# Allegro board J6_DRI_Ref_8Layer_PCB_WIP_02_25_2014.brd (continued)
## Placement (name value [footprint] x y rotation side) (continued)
TP1MA1  TP_VIA_MEM3  [TP1-18RD8]  34.28 26.49 0 top
TP1MA2  TP_VIA_MEM3  [TP1-18RD8]  36.73 25.75 0 top
TP1MA3  TP_VIA_MEM3  [TP1-18RD8]  31.8 25.7 0 top
TP1MA4  TP_VIA_MEM3  [TP1-18RD8]  34.28 25.69 0 top
TP1MA5  TP_VIA_MEM3  [TP1-18RD8]  28.68 25.69 0 top
TP1MA6  TP_VIA_MEM3  [TP1-18RD8]  31.08 25.69 0 top
TP1MA7  TP_VIA_MEM3  [TP1-18RD8]  30.28 24.89 0 top
TP1MA8  TP_VIA_MEM3  [TP1-18RD8]  33.17 24.21 0 top
TP1MA9  TP_VIA_MEM3  [TP1-18RD8]  29.48 24.09 0 top
TP1MA10  TP_VIA_MEM3  [TP1-18RD8]  30.28 24.09 0 top
TP1MA11  TP_VIA_MEM3  [TP1-18RD8]  34.28 24.09 0 top
TP1MA12  TP_VIA_MEM3  [TP1-18RD8]  35.08 23.29 0 top
TP1MA13  TP_VIA_MEM3  [TP1-18RD8]  33.05 22.63 0 top
TP1MA14  TP_VIA_MEM3  [TP1-18RD8]  30.28 22.49 0 top
TP1MA15  TP_VIA_MEM3  [TP1-18RD8]  31.73 22.42 0 top
TP1MA16  TP_VIA_MEM3  [TP1-18RD8]  36.54 21.95 0 top
TP1MA17  TP_VIA_MEM3  [TP1-18RD8]  30.28 21.69 0 top
TP1MA18  TP_VIA_MEM3  [TP1-18RD8]  34.28 21.69 0 top
TP1MA19  TP_VIA_MEM3  [TP1-18RD8]  31.78 21.4 0 top
TP1MA20  TP_VIA_MEM3  [TP1-18RD8]  33.3 20.91 0 top
TP1MA21  TP_VIA_MEM3  [TP1-18RD8]  29.48 20.89 0 top
TP1MA22  TP_VIA_MEM3  [TP1-18RD8]  35.08 20.09 0 top
TP1MA23  TP_VIA_MEM3  [TP1-18RD8]  31.08 19.84 0 top
TP1MA24  TP_VIA_MEM3  [TP1-18RD8]  33.43 19.76 0 top
TP1MA25  TP_VIA_MEM3  [TP1-18RD8]  30.43 19.57 0 top
TP1MA26  TP_VIA_MEM3  [TP1-18RD8]  34.06 19 0 top
TP1MA27  TP_VIA_MEM3  [TP1-18RD8]  31.48 18.49 0 top
TP1MB1  TP_VIA_MEM3  [TP1-18RD8]  46.98 26.49 0 top
TP1MB2  TP_VIA_MEM3  [TP1-18RD8]  49.43 25.75 0 top
TP1MB3  TP_VIA_MEM3  [TP1-18RD8]  44.5 25.7 0 top
TP1MB4  TP_VIA_MEM3  [TP1-18RD8]  46.98 25.69 0 top
TP1MB5  TP_VIA_MEM3  [TP1-18RD8]  41.38 25.69 0 top
TP1MB6  TP_VIA_MEM3  [TP1-18RD8]  43.78 25.69 0 top
TP1MB7  TP_VIA_MEM3  [TP1-18RD8]  42.98 24.89 0 top
TP1MB8  TP_VIA_MEM3  [TP1-18RD8]  45.87 24.21 0 top
TP1MB9  TP_VIA_MEM3  [TP1-18RD8]  42.18 24.09 0 top
TP1MB10  TP_VIA_MEM3  [TP1-18RD8]  42.98 24.09 0 top
TP1MB11  TP_VIA_MEM3  [TP1-18RD8]  46.98 24.09 0 top
TP1MB12  TP_VIA_MEM3  [TP1-18RD8]  47.78 23.29 0 top
TP1MB13  TP_VIA_MEM3  [TP1-18RD8]  45.75 22.63 0 top
TP1MB14  TP_VIA_MEM3  [TP1-18RD8]  42.98 22.49 0 top
TP1MB15  TP_VIA_MEM3  [TP1-18RD8]  44.43 22.42 0 top
TP1MB16  TP_VIA_MEM3  [TP1-18RD8]  49.24 21.95 0 top
TP1MB17  TP_VIA_MEM3  [TP1-18RD8]  42.98 21.69 0 top
TP1MB18  TP_VIA_MEM3  [TP1-18RD8]  46.98 21.69 0 top
TP1MB19  TP_VIA_MEM3  [TP1-18RD8]  44.48 21.4 0 top
TP1MB20  TP_VIA_MEM3  [TP1-18RD8]  46 20.91 0 top
TP1MB21  TP_VIA_MEM3  [TP1-18RD8]  42.18 20.89 0 top
TP1MB22  TP_VIA_MEM3  [TP1-18RD8]  47.78 20.09 0 top
TP1MB23  TP_VIA_MEM3  [TP1-18RD8]  43.78 19.84 0 top
TP1MB24  TP_VIA_MEM3  [TP1-18RD8]  46.13 19.76 0 top
TP1MB25  TP_VIA_MEM3  [TP1-18RD8]  43.13 19.57 0 top
TP1MB26  TP_VIA_MEM3  [TP1-18RD8]  46.76 19 0 top
TP1MB27  TP_VIA_MEM3  [TP1-18RD8]  44.18 18.49 0 top
TP1MC1  TP_VIA_MEM2  [TP1-18RD8]  56.65 27.07 0 top
TP1MC2  TP_VIA_MEM2  [TP1-18RD8]  58.25 27.07 0 top
TP1MC3  TP_VIA_MEM2  [TP1-18RD8]  60.65 27.07 0 top
TP1MC4  TP_VIA_MEM2  [TP1-18RD8]  58.25 26.27 0 top
TP1MC5  TP_VIA_MEM2  [TP1-18RD8]  55.05 25.45 0 top
TP1MC6  TP_VIA_MEM2  [TP1-18RD8]  57.74 25.45 0 top
TP1MC7  TP_VIA_MEM2  [TP1-18RD8]  56.03 24.72 0 top
TP1MC8  TP_VIA_MEM2  [TP1-18RD8]  54.25 24.65 0 top
TP1MC9  TP_VIA_MEM2  [TP1-18RD8]  58.25 24.65 0 top
TP1MC10  TP_VIA_MEM2  [TP1-18RD8]  54.25 23.85 0 top
TP1MC11  TP_VIA_MEM2  [TP1-18RD8]  55.05 23.85 0 top
TP1MC12  TP_VIA_MEM2  [TP1-18RD8]  59.85 23.85 0 top
TP1MC13  TP_VIA_MEM2  [TP1-18RD8]  54.25 23.05 0 top
TP1MC14  TP_VIA_MEM2  [TP1-18RD8]  55.85 23.05 0 top
TP1MC15  TP_VIA_MEM2  [TP1-18RD8]  58.25 23.05 0 top
TP1MC16  TP_VIA_MEM2  [TP1-18RD8]  58.25 22.25 0 top
TP1MC17  TP_VIA_MEM2  [TP1-18RD8]  59.05 22.25 0 top
TP1MC18  TP_VIA_MEM2  [TP1-18RD8]  54.25 21.45 0 top
TP1MC19  TP_VIA_MEM2  [TP1-18RD8]  55.85 21.45 0 top
TP1MC20  TP_VIA_MEM2  [TP1-18RD8]  58.25 21.45 0 top
TP1MC21  TP_VIA_MEM2  [TP1-18RD8]  59.05 21.45 0 top
TP1MC22  TP_VIA_MEM2  [TP1-18RD8]  55.05 20.65 0 top
TP1MC23  TP_VIA_MEM2  [TP1-18RD8]  55.85 19.85 0 top
TP1MC24  TP_VIA_MEM2  [TP1-18RD8]  58.25 19.85 0 top
TP1MC25  TP_VIA_MEM2  [TP1-18RD8]  59.05 19.85 0 top
TP1MC26  TP_VIA_MEM2  [TP1-18RD8]  55.91 19 0 top
TP2  NP  [TP20]  46.81 179.66 270 top
TP2MA1  TP_VIA_MEM0  [TP1-18RD8]  81.05 28.04 180 top
TP2MA2  TP_VIA_MEM0  [TP1-18RD8]  81.41 27.56 180 top
TP2MA3  TP_VIA_MEM0  [TP1-18RD8]  82.22 27.54 180 top
TP2MA4  TP_VIA_MEM0  [TP1-18RD8]  82.07 26.9 180 top
TP2MA5  TP_VIA_MEM0  [TP1-18RD8]  80.67 26.7 180 top
TP2MA6  TP_VIA_MEM0  [TP1-18RD8]  81.31 26.49 180 top
TP2MA7  TP_VIA_MEM0  [TP1-18RD8]  82.14 25.94 180 top
TP2MA8  TP_VIA_MEM0  [TP1-18RD8]  80.72 25.86 180 top
TP2MA9  TP_VIA_MEM0  [TP1-18RD8]  81.37 25.35 180 top
TP2MA10  TP_VIA_MEM0  [TP1-18RD8]  80.8 24.97 180 top
TP2MA11  TP_VIA_MEM0  [TP1-18RD8]  82.19 24.72 180 top
TP2MA12  TP_VIA_MEM0  [TP1-18RD8]  81.56 24.34 0 top
TP2MA13  TP_VIA_MEM0  [TP1-18RD8]  80.72 24.11 180 top
TP2MA14  TP_VIA_MEM0  [TP1-18RD8]  82.07 23.65 180 top
TP2MA15  TP_VIA_MEM0  [TP1-18RD8]  81.05 23.32 180 top
TP2MA16  TP_VIA_MEM0  [TP1-18RD8]  81.43 22.81 180 top
TP2MA17  TP_VIA_MEM0  [TP1-18RD8]  82.07 22.68 180 top
TP2MA18  TP_VIA_MEM0  [TP1-18RD8]  80.67 22.28 180 top
TP2MA19  TP_VIA_MEM0  [TP1-18RD8]  81.94 21.74 180 top
TP2MA20  TP_VIA_MEM0  [TP1-18RD8]  81.33 21.54 180 top
TP2MA21  TP_VIA_MEM0  [TP1-18RD8]  80.85 21.19 180 top
TP2MA22  TP_VIA_MEM0  [TP1-18RD8]  81.74 20.65 180 top
TP2MA23  TP_VIA_MEM0  [TP1-18RD8]  82.63 20.37 180 top
TP2MA24  TP_VIA_MEM0  [TP1-18RD8]  81.15 20.35 180 top
TP2MA25  TP_VIA_MEM0  [TP1-18RD8]  81.94 19.51 180 top
TP2MA26  TP_VIA_MEM0  [TP1-18RD8]  82.58 19.51 180 top
TP2MA27  TP_VIA_MEM0  [TP1-18RD8]  80.29 19.26 180 top
TP2MB1  TP_VIA_MEM1  [TP1-18RD8]  95.4 28.04 180 top
TP2MB2  TP_VIA_MEM1  [TP1-18RD8]  95.76 27.56 180 top
TP2MB3  TP_VIA_MEM1  [TP1-18RD8]  96.57 27.54 180 top
TP2MB4  TP_VIA_MEM1  [TP1-18RD8]  96.42 26.9 180 top
TP2MB5  TP_VIA_MEM1  [TP1-18RD8]  95.02 26.7 180 top
TP2MB6  TP_VIA_MEM1  [TP1-18RD8]  95.66 26.49 180 top
TP2MB7  TP_VIA_MEM1  [TP1-18RD8]  96.49 25.96 180 top
TP2MB8  TP_VIA_MEM1  [TP1-18RD8]  95.07 25.86 180 top
TP2MB9  TP_VIA_MEM1  [TP1-18RD8]  95.72 25.35 180 top
TP2MB10  TP_VIA_MEM1  [TP1-18RD8]  95.15 24.97 180 top
TP2MB11  TP_VIA_MEM1  [TP1-18RD8]  96.55 24.72 180 top
TP2MB12  TP_VIA_MEM1  [TP1-18RD8]  95.91 24.34 0 top
TP2MB13  TP_VIA_MEM1  [TP1-18RD8]  95.07 24.11 180 top
TP2MB14  TP_VIA_MEM1  [TP1-18RD8]  96.42 23.65 180 top
TP2MB15  TP_VIA_MEM1  [TP1-18RD8]  95.4 23.32 180 top
TP2MB16  TP_VIA_MEM1  [TP1-18RD8]  95.78 22.81 180 top
TP2MB17  TP_VIA_MEM1  [TP1-18RD8]  96.42 22.68 180 top
TP2MB18  TP_VIA_MEM1  [TP1-18RD8]  95.02 22.28 180 top
TP2MB19  TP_VIA_MEM1  [TP1-18RD8]  96.29 21.74 180 top
TP2MB20  TP_VIA_MEM1  [TP1-18RD8]  95.68 21.54 180 top
TP2MB21  TP_VIA_MEM1  [TP1-18RD8]  95.2 21.19 180 top
TP2MB22  TP_VIA_MEM1  [TP1-18RD8]  96.09 20.65 180 top
TP2MB23  TP_VIA_MEM1  [TP1-18RD8]  96.98 20.37 180 top
TP2MB24  TP_VIA_MEM1  [TP1-18RD8]  95.5 20.35 180 top
TP2MB25  TP_VIA_MEM1  [TP1-18RD8]  96.29 19.51 180 top
TP2MB26  TP_VIA_MEM1  [TP1-18RD8]  96.93 19.51 180 top
TP2MB27  TP_VIA_MEM1  [TP1-18RD8]  94.64 19.26 180 top
TP2MC1  TP_VIA_MEM2  [TP1-18RD8]  53.07 26.25 0 top
TP22  NP  [TP20]  0.97 87.45 270 top
TP23  NP  [TP20]  12.65 86.95 270 top
TP24  NP  [TP20]  118.31 85.04 180 top
TP27  NP  [TP20]  26.49 94.82 0 top
TP30  NP  [TP20]  134.95 84.91 180 top
TP31  NP  [TP20]  134.95 85.93 180 top
TP32  NP  [TP20]  118.31 86.18 180 top
TP39  NP  [TP20]  30.56 77.93 0 top
TP41  NP  [TP20]  118.82 69.29 180 top
TP42  NP  [TP20]  125.55 65.86 180 top
TP43  NP  [TP20]  127.71 65.86 180 top
TP44  NP  [TP20]  0.97 65.61 270 top
TP45  NP  [TP20]  13.16 65.36 270 top
TP46  NP  [TP20]  0.97 64.59 270 top
TP47  NP  [TP20]  12.65 64.59 270 top
TP48  NP  [TP20]  13.16 63.83 270 top
TP49  NP  [TP20]  0.97 63.58 270 top
TP51  NP  [TP20]  157.53 217.15 0 top
TP52  NP  [TP20]  37.67 60.91 0 top
TP54  NP  [TP20]  162 217.15 0 top
TP55  NP  [TP20]  38.81 57.74 0 top
TP57  NP  [TP20]  39.07 51.13 0 top
TP58  NP  [TP20]  160.88 217.15 0 top
TP59  NP  [TP20]  159.77 217.15 0 top
TP60  NP  [TP20]  158.65 217.15 0 top
TP61  NP  [TP20]  6.81 41.73 270 top
TP62  NP  [TP20]  124.54 25.86 0 top
TP63  NP  [TP20]  2.54 15.24 0 top
TP64  NP  [TP20]  6.81 15.24 180 top
TP76  NP  [TP20]  156.41 217.15 0 top
TP77  NP  [TP20]  155.3 217.15 0 top
TP78  NP  [TP20]  154.18 217.15 0 top
TP97  TESTPOINT  [TP1-18RD8]  165.2 217.12 0 top
TP98  TESTPOINT  [TP1-18RD8]  164.14 217.12 0 top
TP99  TESTPOINT  [TP1-18RD8]  163.09 217.12 0 top
TP100  TESTPOINT  [TP1-18RD8]  153.09 217.12 0 top
TP101  TESTPOINT  [TP1-18RD8]  147.81 217.12 0 top
TP102  TESTPOINT  [TP1-18RD8]  148.86 217.12 0 top
TP103  TESTPOINT  [TP1-18RD8]  144.64 217.12 0 top
TP104  TESTPOINT  [TP1-18RD8]  146.75 217.12 0 top
TP105  TESTPOINT  [TP1-18RD8]  149.92 217.12 0 top
TP106  TESTPOINT  [TP1-18RD8]  143.58 217.12 0 top
TP107  TESTPOINT  [TP1-18RD8]  145.69 217.12 0 top
TP108  TESTPOINT  [TP1-18RD8]  150.98 217.12 0 top
TP109  TESTPOINT  [TP1-18RD8]  152.03 217.12 0 top
TP110  TESTPOINT  [TP1-18RD8]  166.26 217.12 0 top
U3  DS90UR905QSQE/NOPB  [QFN48-11X35]  110.31 160.48 90 top
U6  74LVC1G08DCK  [DCK-5]  106.5 146 270 top
U8  RBO40_40G  [DPAK3-55X120-4]  160.48 159.21 270 top
U18  S25FL256SAGMFV001  [SO16-25X75-300]  83.26 112.73 90 top
U23  TPS43351QDAPRQ1  [DAP38]  149.81 115.52 270 top
U35  SN74AVC8T245RHL  [RHL24-PVQFN-TI]  16.33 92.92 90 top
U36  TPS2065D  [SO8-25X75]  25.86 90.5 270 top
U37  TPS3808G09DBVR  [DBV6-27X39-6]  137.49 89.11 0 top
U41  SN74AVC4T245RGYR  [RGY16-12X34]  16.33 84.91 90 top
U43  TPS2065D  [SO8-25X75]  25.86 81.87 270 top
U44  TPS3808G09DBVR  [DBV6-27X39-6]  43.13 81.36 90 top
U45  TPS659039  [ZWS169-13P8]  127.58 77.42 0 top
U46  SN74AVC8T245RHL  [RHL24-PVQFN-TI]  16.33 77.29 90 top
U48  SN74AVC4T245RGYR  [RGY16-12X34]  16.33 69.29 90 top
U50  PCA9306/PCA9306-Q1  [DCU8-10X50]  16.46 62.44 180 top
U52  DRA7XX  [BGA-ZKK-6334-P760]  67.13 58.85 270 top
U54  HVDA551-Q1  [SO8-25X75]  15.06 54.43 270 top
U55  TPS77018DBVT  [DBV5-27X39]  159.33 51.39 180 top
U56  TPS74801  [DRC10-11X33]  4.14 51.26 0 top
U59  TLV320AIC3106  [RGZ48-11X34]  149.68 45.8 270 top
U62  74LVC1G08DCK  [DCK-5]  102.31 40.59 90 top
U63  TPS57112QRTERQ1  [RTE16-12X34]  8.08 38.31 270 top
U64  TPS51200  [DRC10-11X33]  6.81 27.76 0 top
U65  MT41K256M16HA-125 IT:E  [BGA6X16-P8-RE-PKG]  32.28 26.49 0 top
U66  MT41K256M16HA-125 IT:E  [BGA6X16-P8-RE-PKG]  44.98 26.49 0 top
U67  MT41K128M8JP-15E:AAT  [BGA6X13-P8-RA-PKG]  57.05 25.86 0 top
U68  MT41K256M8DA-15E:M ATT  [BGA6X13-P8-RA-PKG]  81.43 25.86 0 top
U69  MT41K256M8DA-15E:M ATT  [BGA6X13-P8-RA-PKG]  95.78 25.86 0 top
U72  TPD4S014DSQ  [DSQ10-SON]  59.77 175.21 270 bottom
U73  TPD4S014DSQ  [DSQ10-SON]  44.91 176.99 270 bottom
U77  TPD2E001DRL-Q1  [DRL5-12X40]  140.28 158.32 0 bottom
U78  TPD2E001DRL-Q1  [DRL5-12X40]  135.71 158.32 0 bottom
U79  TPD2E001DRL-Q1  [DRL5-12X40]  131.14 158.32 0 bottom
U92  TPS22965DSG  [DSG8-11X20]  122.38 102.31 0 bottom
U100  TXS0108EPW  [PW20-14X70]  6.81 75.39 180 bottom
U101  SN74AVC2T45DCT  [DCT8-14X70]  136.47 67.26 270 bottom
U102  TPS3808G09DBVR  [DBV6-27X39-6]  109.04 66.63 180 bottom
U104  SN74LVC1T45  [DCK-17X60-6]  7.32 63.83 90 bottom
U105  24WC256  [SO8-25X75-295]  161.49 61.8 0 bottom
U110  SN74LVC1G04DCK  [DCK-5]  13.79 56.21 90 bottom
U115  MT41K256M8DA-15E:M ATT  [BGA6X13-P8-RA-PKG]  95.78 25.86 180 bottom
U116  MT41K256M8DA-15E:M ATT  [BGA6X13-P8-RA-PKG]  81.43 25.86 180 bottom
U117  TMP102AIDRLT  [DRL6-12X30]  67 197.26 0 top
U121  MTFC16GJVEC-4M-169WFBGA  [FBGA153-169-P5-COMBO]  7.43 204.98 0 top
U122  SN65HVDA100-Q1  [SO8-25X75]  127.33 158.32 0 bottom
U123  HVDA551-Q1  [SO8-25X75]  123.52 161.75 180 bottom
U129  74LVC1G08DCK  [DCK-5]  69.83 197.38 0 top
U130  74LVC1G08DCK  [DCK-5]  72.71 197.38 0 top
U131  TPD2E001DRL-Q1  [DRL5-12X40]  75.58 197.38 0 top
U132  TVP5150AM1  [PBS32-12X57]  19.37 200.18 0 top
Y3  32.768KHz  [XTAL4-23X47-SSP-T7]  37.41 63.45 180 top
Y4  Crystal_CM519_CTS407  [XTAL2-CM519-DUAL-CTS407]  134.19 61.55 0 top
Y5  22.5792MHz  [XTAL4-55X87]  32.72 59.39 0 top
Y6  20MHz  [XTAL2-75X94]  42.49 57.36 90 top
Y7  14.31818MHz  [XTAL2-75X94]  53.04 144.73 90 bottom

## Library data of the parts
C5 C6 = CAP: Tolerance: TOLERANCE; User Part Number: USERPART#; signal model: CAP_C402_25_0_1UF_0_1uF
C7 C8 C13 C60 C61 C72 C77 C104 C136 C140 C158 C210-C212 C214 C228 C229 C233-C235 C295 C299 C300 C318 C319 C355 C357 C382 C406 C436 C493 C548 C556 C557 C560 C562 C564 C569 C571 C572 C576 C577 C589 C655-C657 C665 C670 C673 C678 = CAP: Tolerance: X; User Part Number: X
C14-C16 C269 C290 C693 C787 = Cap 100nF Cermc 16V 10% 603_4: Tolerance: TOLERANCE; User Part Number: USERPART#
C45 C47 C49 C50 C440 C462 C468 C480 C481 C501 C504 C509 C519 C520 C529 C734 = CAP NP: Tolerance: X; User Part Number: X
C51 = CAP_POL: Tolerance: X; User Part Number: X
C52 C62 C63 C154 C156 C174 C188 C191 C192 C201 C202 C503 C546 = CAP NP: User Part Number: X; Tolerance: X
C67 = CAP NP: Tolerance: TOLERANCE; User Part Number: USERPART#; room: SPI FLASH
C71 C74 C683 = C_0: Tolerance: X; User Part Number: X
C76 C78 C110 C117 C137-C139 C143 C148 C231 C232 C273 C280 C301-C307 C309 C314 C329 C330 C348 C485 C508 C514 C521 C522 C528 C535 C537 C541 C549 C550 C553 C559 C563 C570 C574 C578 C580 C584 C609 C708 C716-C721 C785 C786 C792-C794 C797 C800 C801 = CAP: Tolerance: TOLERANCE; User Part Number: USERPART#
C79 C86 C213 C325 C340 C356 C460 = CAP: User Part Number: X; Tolerance: X
C80 = CAP NP: User Part Number: USERPART#; Tolerance: TOLERANCE; room: USB
C87 C89 C107 C109 C112 C118 C119 C149 C150 C155 C157 C179 C186 C187 C365 C366 C369 C372 C384 C385 C387 C389 C396 C405 C411 C435 C463 C466 C469 C473-C475 C492 C495 C532 C579 C607 C658 C659 = CAP NP: User Part Number: USERPART#; Tolerance: TOLERANCE
C90-C96 C105 C108 C111 C359 C360 C367 C373 C374 C393-C395 C453 C456 C465 C478 C483 C487 = NPCap_0: User Part Number: X; Tolerance: X
C99 C101-C103 C346 C352 C381 C403 C407 C408 C430 C431 C433 = C_2.2uF/0402/6.3V_X5R_0402: User Part Number: USERPART#; Tolerance: TOLERANCE
C100 C434 = C_100nF/0402/6.3V_X5R_0402: User Part Number: USERPART#; Tolerance: TOLERANCE
C106 C113 = Cap 18pF Cermc 50V 5% 603_0: User Part Number: USERPART#; Tolerance: TOLERANCE
C115 C116 = C_12pF/0402/50V_COG_0402: User Part Number: USERPART#; Tolerance: TOLERANCE
C123 C124 C126 C128 = CAP NP_3: User Part Number: USERPART#; Tolerance: TOLERANCE
C130 C144 C152 = CAPACITOR POL_0: User Part Number: X; Tolerance: X; room: aic3106
C131 C132 C134 C141 C142 C151 C153 C173 C558 C565-C568 C575 C648 = CAP NP: User Part Number: USERPART#; Tolerance: TOLERANCE; room: aic3106
C133 = CAP NP_2: User Part Number: X; Tolerance: X; room: aic3106
C147 C293 C371 C401 C402 C416 C417 C423 C424 C438 C439 C442 C443 C445 C449 C451 C454 C457 C464 C467 C470 C471 C482 C484 C486 C489 C494 C496 C500 C502 C510 C511 C524 C526 C530 C538 C539 C545 C696 C733 C735 C789-C791 = CAP NP: Tolerance: TOLERANCE; User Part Number: USERPART#
C159-C165 C169-C172 C175 C177 C180 C184 C185 C189 C190 C195-C197 C199 C203-C207 C418 C426 C429 C490 C582 C585 C586 C593 C596 C615-C619 C627 C630 C631 C635 C637 C643-C645 C650 C654 C662 C663 C672 C674-C677 C679 = CAP NP_0: Tolerance: X; User Part Number: X
C166 C167 C208 C629 C652 = CAP NP_0: Tolerance: X; User Part Number: X; room: ddr bank1 caps
C168 C647 = CAP: Tolerance: X; User Part Number: X; room: aic3106
C176 C178 C181 C198 C200 C209 C581 C592 C595 C626 C628 C634 C636 C642 C649 C651 C653 C660 C661 C664 C666-C669 C671 = CAP NP_0: Tolerance: X; User Part Number: X; room: ddr bank0 caps
C182 C183 C193 C194 C413 C419 C420 C422 C425 C427 C491 C497 C583 C587 C588 C590 C591 C594 C597 C598 C600 C602 C603 C605 C606 C608 C610-C614 C621-C625 C632 C633 C638-C641 C680 = CAP NP_0: Tolerance: TOLERANCE; User Part Number: USERPART#
C236 = CAP: Tolerance: TOLERANCE; User Part Number: USERPART#; room: USB
C274 = Cap 100nF Cermc 16V 10% 603_4: Tolerance: TOLERANCE; User Part Number: USERPART#; room: PATA MUX
C326-C328 C459 = C_10uF/6.3V_X5R_0603: User Part Number: X; Tolerance: X
C331 C332 C335 C344 C345 C351 C358 C404 C446-C448 C472 C479 C525 C527 C531 C540 C573 = CAP: User Part Number: USERPART#; Tolerance: TOLERANCE
C338 C341 C342 C353 C354 C375 C376 C379 C380 = C_4.7uF/0402/6.3V_X5R_0402: Tolerance: X; User Part Number: X
C349 C350 C377 C378 C409 C410 = C_10uF/6.3V_X5R_0603: Tolerance: X; User Part Number: X
C363 C364 C368 C370 C386 C388 C390-C392 C498 = NPCap_0: User Part Number: USERPART#; Tolerance: TOLERANCE
C399 C400 C412 C414 C415 C437 C444 C450 C455 C458 C461 C507 C518 C542 = NPCap_0: Tolerance: TOLERANCE; User Part Number: USERPART#
C421 = CAP NP_2: Tolerance: X; User Part Number: X
C432 C810 = C_2.2uF/0402/6.3V_X5R_0402: Tolerance: X; User Part Number: X
C441 = CAP NP_2: User Part Number: USERPART#; Tolerance: TOLERANCE
C477 C506 C512 C516 C517 = CAP NP: Tolerance: X; User Part Number: X; room: LDS
C513 = CAP .1 uF 10% 0603: User Part Number: USERPART#; Tolerance: TOLERANCE
C515 = Cap 100nF Cermc 16V 10% 603_3: User Part Number: USERPART#; Tolerance: TOLERANCE
C523 = CAP .1 uF 10% 0603: Tolerance: TOLERANCE; User Part Number: USERPART#
C536 = C_0: User Part Number: USERPART#; Tolerance: TOLERANCE; room: aic3106
C561 = CAP: Tolerance: X; User Part Number: X; room: SPI FLASH
C599 = SC10N16V2KX_0: User Part Number: USERPART#; Tolerance: TOLERANCE
C601 = SC10N16V2KX_0: User Part Number: USERPART#; Tolerance: TOLERANCE; room: ddr bank0 caps
C715 C788 = 0_1.1uF Chip Cap: Tolerance: TOLERANCE; User Part Number: USERPART#
C795 C796 = 0_1.1uF Chip Cap: Tolerance: X; User Part Number: X
C798 C799 = CAP NP_3: Tolerance: TOLERANCE; User Part Number: USERPART#
D1 D2 = DIODE: Tolerance: X; User Part Number: X
E1-E3 E8 E9 = NFM_1: User Part Number: PART#; Tolerance: TOL
E4-E6 E10 E11 = NFM_1: Tolerance: TOL; User Part Number: PART#
F1 = NANO-SMF_0: User Part Number: X; Tolerance: X
FL1 FL4 = DLW21SN121HQ2: Tolerance: TOL; User Part Number: PART#; signal model: DLW21SN121HQ2_EMI_36X15_DLW21_D_DLW21SN121HQ2
FL5 = DLW21SN121HQ2: Tolerance: TOL; User Part Number: PART#; signal model: DLW21SN900HQ2_EMI_36X15_DLW21_D_DLW21SN900HQ2
J17 = MIPI-QTH-030_1: User Part Number: PART#; Tolerance: TOL
J21 J24 = HEADER 2: Tolerance: X; User Part Number: X
L2 L3 L23 = FERRITE CHIP_0: Tolerance: X; User Part Number: X
L6 = INDUCTOR
L7 = INDUCTOR: Tolerance: TOLERANCE; User Part Number: USERPART#
L8 = INDUCTOR_3: User Part Number: X; Tolerance: X; room: USB
L9 L10 = IND_0.47uH_LQM2MPR47NG0: Tolerance: TOLERANCE; User Part Number: USERPART#
L11 = IND_0.47uH_DFE252010C_R47N: Tolerance: TOLERANCE; User Part Number: USERPART#
L12 = INDUCTOR_3: User Part Number: X; Tolerance: X
L13 L15 L17 = IND_1.47uH_DFE252012C_R47N: User Part Number: USERPART#; Tolerance: TOLERANCE
L14 L16 L18 = IND_0.47uH_DFE252010C_R47N: User Part Number: USERPART#; Tolerance: TOLERANCE
L19 L21 L22 = INDUCTOR: User Part Number: X; Tolerance: X; room: aic3106
L20 = INDUCTOR: User Part Number: X; Tolerance: X
L24 L25 = INDUCTOR_0: Tolerance: X; User Part Number: X
P1 = J - SamTec QSH020 40pin_2
P5 = SFM-105-02-S-D-LC_0: User Part Number: PART#; Tolerance: TOL
P9 = HEADER 50x2
P12 = Kycon ST-3500_0: room: aic3106
P14 = MM_CARD_0: User Part Number: X; Tolerance: X
Q1-Q4 = MOSFET_CSD16406Q3_0: User Part Number: X; Tolerance: X
Q5 = SUD50P04-08: Tolerance: TOLERANCE; User Part Number: USERPART#
R1 R8-R11 R20 R22 R35 R100 R151-R153 R182-R184 R204 R216 R232 R256 R301 R302 R307 R332 R333 R338 R407 R417 R429 R494 R495 R529 R548 R605 R618 R620 R624 R629 R633 R636 R651 R652 R758-R762 R770 R771 R828-R832 R834-R846 R848-R851 R859 R864-R867 R911-R913 R917-R931 R933-R942 R944-R950 R957-R963 = R: User Part Number: USERPART#; Tolerance: TOLERANCE
R14-R19 R327 = RESISTOR: User Part Number: USERPART#; Tolerance: TOLERANCE; room: micro sd
R80-R95 R110-R125 = R_1: Tolerance: TOLERANCE; User Part Number: USERPART#; room: boot switches
R106 R420 = R: User Part Number: USERPART#; Tolerance: TOLERANCE; room: pcie
R126 R127 R143 R145-R147 R453 R472 = RESISTOR: User Part Number: X; Tolerance: X
R128 R131 R442 = RESISTOR: User Part Number: USERPART#; Tolerance: TOLERANCE; room: SPI FLASH
R134 R135 = RESISTOR
R138 R140 R144 R340-R345 R404-R406 R410 R414 R422 R423 R426 R428 R433 R450 R451 R454-R457 R461 R463 R464 R473 R? = RESISTOR: User Part Number: USERPART#; Tolerance: TOLERANCE
R154 = R: Tolerance: TOLERANCE; User Part Number: USERPART#; room: usb
R157 R178 R179 R196 R200 R222 R269 R272 R273 R277 R279 R280 R282 R283 R286 R288-R292 R515 R519-R524 R528 R530-R532 R554 R558-R562 R567 R573-R575 R577 R581 R584 R587 R600 R615 R617 R689 R693-R695 R708 R709 R714 R715 R757 R766 R914 R915 = R: Tolerance: TOLERANCE; User Part Number: USERPART#
R191 R483 R516 R518 = R_10K_0402_1%_Multi: Tolerance: TOLERANCE; User Part Number: USERPART#
R192 R193 = R_0_0402_1%_Multi: Tolerance: TOLERANCE; User Part Number: USERPART#
R194 R205-R211 R513 R514 R533-R535 R537 R549 R565 R570 R588-R592 R782-R785 R956 = R_10K_0402_1%_Multi: User Part Number: USERPART#; Tolerance: TOLERANCE
R238 R255 R278 R774 = R: User Part Number: X; Tolerance: X
R241 R244 = R_3: Tolerance: X; User Part Number: X
R245 R632 = R: Tolerance: TOLERANCE; User Part Number: USERPART#; room: jtag
R249-R253 R257 R260 R262 R266 R287 R642-R644 R654 R659 R664 R668 R671-R673 R675 R702 = R_0: Tolerance: TOLERANCE; User Part Number: USERPART#; room: aic3106
R254 = RESISTOR: Tolerance: TOLERANCE; User Part Number: USERPART#; room: aic3106
R276 = R: Tolerance: X; User Part Number: X
R281 R697 = R: Tolerance: TOLERANCE; User Part Number: USERPART#; room: aic3106
R481 = R: Tolerance: TOLERANCE; User Part Number: USERPART#; room: USB
R555 R596 R623 = R_2: Tolerance: TOLERANCE; User Part Number: USERPART#
R569 R599 R625 = R_1: User Part Number: USERPART#; Tolerance: TOLERANCE
R576 R578 = R_1: Tolerance: TOLERANCE; User Part Number: USERPART#
R583 = RESISTOR: Tolerance: TOLERANCE; User Part Number: USERPART#
R593 R597 R603 = RESISTOR_0: Tolerance: TOLERANCE; User Part Number: USERPART#
R627 R634 R635 R650 R653 = R: User Part Number: USERPART#; Tolerance: TOLERANCE; room: jtag
R684 R687 = 1KR2F: Tolerance: TOLERANCE; User Part Number: USERPART#
R685 R688 = 1KR2F_0: Tolerance: TOLERANCE; User Part Number: USERPART#; room: ddr bank0 caps
R691 R692 = R_0: Tolerance: TOLERANCE; User Part Number: USERPART#
R727 R728 = R: User Part Number: USERPART#; Tolerance: TOLERANCE; signal model: R_R402_25_10_10
R800-R802 = R_0: User Part Number: USERPART#; Tolerance: TOLERANCE
R943 R951 R953 R954 = R_805: User Part Number: X; Tolerance: X
R952 R955 = R_805: User Part Number: USERPART#; Tolerance: TOLERANCE
RN2 RN4 RN6 RN13 RN15 RN17 = R-Pak4_0: User Part Number: PART#; Tolerance: TOL
RN3 RN5 RN7 RN12 RN14 RN16 = R-Pak4_0: User Part Number: PART#; Tolerance: TOL; room: ddr bank0
RN20-RN25 RN30-RN33 = R-PACK4: Tolerance: TOL; User Part Number: PART#
SW4 = SW PUSHBUTTON_3: Tolerance: X; User Part Number: X
TP1 TP2 TP27 TP39 TP51 TP62-TP64 TP76-TP78 = TestPoint1_0
TP1MA1-TP1MA27 TP1MB1-TP1MB27 = TP_VIA_MEM3_0
TP1MC1-TP1MC26 TP2MC1 = TP_VIA_MEM2_0
TP2MA1-TP2MA27 = TP_VIA_MEM0_0
TP2MB1-TP2MB27 = TP_VIA_MEM1_0
TP22 TP23 TP44-TP49 TP52 TP54 TP55 TP57-TP61 TP97-TP110 = TESTPOINT
TP24 TP30-TP32 TP41-TP43 = TP_0
U3 = DS90UH925Q_1
U6 = 1G08: Tolerance: TOL; User Part Number: PART#; room: NAND FLASH
U8 = RBO40_1: Tolerance: TOLERANCE; User Part Number: USERPART#
U18 = SPI_EEPROM_1: Tolerance: X; User Part Number: X; room: SPI FLASH
U23 = TPS43351QDAPRQ1_0
U35 U46 = SN74AVC8T245_1: User Part Number: PART#; Tolerance: TOL
U36 = tps2061_1: Tolerance: X; User Part Number: X; room: USB
U37 U44 = TPS3808G09DBVR_0: Tolerance: X; User Part Number: X
U41 U48 = SN74AVC4T245RGYR_0: Tolerance: X; User Part Number: X
U43 = tps2061_1: Tolerance: X; User Part Number: X; room: usb
U45 = TPS659038_2
U50 = PCA9306
U52 = VAYU_DEC_3_2
U54 = SN65HVDA541: Tolerance: X; User Part Number: X
U55 = TPS76901_1: Tolerance: X; User Part Number: X; room: aic3106
U56 = U-TPS78601_AJUST - 1_3.5A LDO: Tolerance: X; User Part Number: X
U59 = TLV320AIC3106_0: room: aic3106
U62 = 1G08: User Part Number: PART#; Tolerance: TOL
U63 = TPS57112QRTERQ1_0: Tolerance: X; User Part Number: X
U64 = TPS51200: Tolerance: X; User Part Number: X
U65 U66 = DDR3_96BALL_X16_0
U67-U69 U115 U116 = EDJ1108DBSE_1
U72 U73 = TPD4S014DSQ: Tolerance: TOL; User Part Number: PART#
U77 U78 U131 = TPDE0001RSE_0: Tolerance: TOL; User Part Number: PART#
U79 = TPDE0001RSE_0: Tolerance: TOL; User Part Number: PART#; room: SPI FLASH
U92 = TPS22965DSG: User Part Number: X; Tolerance: X
U100 = TXB0108PWR_0: User Part Number: X; Tolerance: X
U101 = SN74AVC2T45DCT: Tolerance: X; User Part Number: X
U102 = TPS3808G09DBVR_0: User Part Number: X; Tolerance: X
U104 = TMP_1: User Part Number: PART#; Tolerance: TOL
U105 = 24WC256: Tolerance: X; User Part Number: X
U110 = SN74LVC1GU04_1: User Part Number: PART#; Tolerance: TOL
U117 = TMP102AIDRLT: Tolerance: TOL; User Part Number: PART#
U121 = MTFC16GJVEC-4M-169WFBGA
U122 = SN65HVDA100-Q1: User Part Number: X; Tolerance: X
U123 = SN65HVDA541: User Part Number: X; Tolerance: X
U129 U130 = 1G08: Tolerance: TOL; User Part Number: PART#
U132 = TVP5150AM1
Y3 Y6 = CRYSTAL_0
Y4 = Crystal_CM519_CTS407
Y5 = CRYSTAL_22.5792MHz
Y7 = CRYSTAL_0: room: ethernet2

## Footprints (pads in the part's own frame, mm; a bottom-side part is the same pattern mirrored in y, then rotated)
BGA6X13-P8-RA-PKG
  round 0.343 smd: A1(-3.2,4.801) A2(-2.4,4.801) A3(-1.6,4.801) A7(1.6,4.801) A8(2.4,4.801) A9(3.2,4.801) B1(-3.2,4) B2(-2.4,4) B3(-1.6,4) B7(1.6,4) B8(2.4,4) B9(3.2,4) C1(-3.2,3.2) C2(-2.4,3.2) C3(-1.6,3.2) C7(1.6,3.2) C8(2.4,3.2) C9(3.2,3.2) D1(-3.2,2.4) D2(-2.4,2.4) D3(-1.6,2.4) D7(1.6,2.4) D8(2.4,2.4) D9(3.2,2.4) E1(-3.2,1.6) E2(-2.4,1.6) E3(-1.6,1.6) E7(1.6,1.6) E8(2.4,1.6) E9(3.2,1.6) F1(-3.2,0.8) F2(-2.4,0.8) F3(-1.6,0.8) F7(1.6,0.8) F8(2.4,0.8) F9(3.2,0.8) G1(-3.2,0) G2(-2.4,0) G3(-1.6,0) G7(1.6,0) G8(2.4,0) G9(3.2,0) H1(-3.2,-0.8) H2(-2.4,-0.8) H3(-1.6,-0.8) H7(1.6,-0.8) H8(2.4,-0.8) H9(3.2,-0.8) J1(-3.2,-1.6) J2(-2.4,-1.6) J3(-1.6,-1.6) J7(1.6,-1.6) J8(2.4,-1.6) J9(3.2,-1.6) K1(-3.2,-2.4) K2(-2.4,-2.4) K3(-1.6,-2.4) K7(1.6,-2.4) K8(2.4,-2.4) K9(3.2,-2.4) L1(-3.2,-3.2) L2(-2.4,-3.2) L3(-1.6,-3.2) L7(1.6,-3.2) L8(2.4,-3.2) L9(3.2,-3.2) M1(-3.2,-4) M2(-2.4,-4) M3(-1.6,-4) M7(1.6,-4) M8(2.4,-4) M9(3.2,-4) N1(-3.2,-4.801) N2(-2.4,-4.801) N3(-1.6,-4.801) N7(1.6,-4.801) N8(2.4,-4.801) N9(3.2,-4.801)
BGA6X16-P8-RE-PKG
  round 0.35 smd: A1(-3.2,6) A2(-2.4,6) A3(-1.6,6) A7(1.6,6) A8(2.4,6) A9(3.2,6) B1(-3.2,5.2) B2(-2.4,5.2) B3(-1.6,5.2) B7(1.6,5.2) B8(2.4,5.2) B9(3.2,5.2) C1(-3.2,4.4) C2(-2.4,4.4) C3(-1.6,4.4) C7(1.6,4.4) C8(2.4,4.4) C9(3.2,4.4) D1(-3.2,3.6) D2(-2.4,3.6) D3(-1.6,3.6) D7(1.6,3.6) D8(2.4,3.6) D9(3.2,3.6) E1(-3.2,2.8) E2(-2.4,2.8) E3(-1.6,2.8) E7(1.6,2.8) E8(2.4,2.8) E9(3.2,2.8) F1(-3.2,2) F2(-2.4,2) F3(-1.6,2) F7(1.6,2) F8(2.4,2) F9(3.2,2) G1(-3.2,1.2) G2(-2.4,1.2) G3(-1.6,1.2) G7(1.6,1.2) G8(2.4,1.2) G9(3.2,1.2) H1(-3.2,0.4) H2(-2.4,0.4) H3(-1.6,0.4) H7(1.6,0.4) H8(2.4,0.4) H9(3.2,0.4) J1(-3.2,-0.4) J2(-2.4,-0.4) J3(-1.6,-0.4) J7(1.6,-0.4) J8(2.4,-0.4) J9(3.2,-0.4) K1(-3.2,-1.2) K2(-2.4,-1.2) K3(-1.6,-1.2) K7(1.6,-1.2) K8(2.4,-1.2) K9(3.2,-1.2) L1(-3.2,-2) L2(-2.4,-2) L3(-1.6,-2) L7(1.6,-2) L8(2.4,-2) L9(3.2,-2) M1(-3.2,-2.8) M2(-2.4,-2.8) M3(-1.6,-2.8) M7(1.6,-2.8) M8(2.4,-2.8) M9(3.2,-2.8) N1(-3.2,-3.6) N2(-2.4,-3.6) N3(-1.6,-3.6) N7(1.6,-3.6) N8(2.4,-3.6) N9(3.2,-3.6) P1(-3.2,-4.4) P2(-2.4,-4.4) P3(-1.6,-4.4) P7(1.6,-4.4) P8(2.4,-4.4) P9(3.2,-4.4) R1(-3.2,-5.2) R2(-2.4,-5.2) R3(-1.6,-5.2) R7(1.6,-5.2) R8(2.4,-5.2) R9(3.2,-5.2) T1(-3.2,-6) T2(-2.4,-6) T3(-1.6,-6) T7(1.6,-6) T8(2.4,-6) T9(3.2,-6)
BGA-ZKK-6334-P760
  round 0.356 smd: A1(-10.803,10.803) A2(-10.002,10.803) A3(-9.202,10.803) A4(-8.402,10.803) A5(-7.602,10.803) A6(-6.802,10.803) A7(-6.002,10.803) A8(-5.202,10.803) A9(-4.402,10.803) A10(-3.602,10.803) A11(-2.802,10.803) A12(-2.002,10.803) A13(-1.201,10.803) A14(-0.401,10.803) A15(0.401,10.803) A16(1.201,10.803) A17(2.002,10.803) A18(2.802,10.803) A19(3.602,10.803) A20(4.402,10.803) A21(5.202,10.803) A22(6.002,10.803) A23(6.802,10.803) A24(7.602,10.803) A25(8.402,10.803) A26(9.202,10.803) A27(10.002,10.803) A28(10.803,10.803) AA1(-10.803,-5.202) AA2(-10.002,-5.202) AA3(-9.202,-5.202) AA4(-8.402,-5.202) AA5(-7.602,-5.202) AA6(-6.802,-5.202) AA7(-6.002,-5.202) AA8(-5.202,-5.202) AA9(-4.402,-5.202) AA10(-3.602,-5.202) AA11(-2.802,-5.202) AA12(-2.002,-5.202) AA13(-1.201,-5.202) AA14(-0.401,-5.202) AA15(0.401,-5.202) AA16(1.201,-5.202) AA17(2.002,-5.202) AA18(2.802,-5.202) AA19(3.602,-5.202) AA20(4.402,-5.202) AA21(5.202,-5.202) AA22(6.002,-5.202) AA23(6.802,-5.202) AA24(7.602,-5.202) AA25(8.402,-5.202) AA26(9.202,-5.202) AA27(10.002,-5.202) AA28(10.803,-5.202) AB1(-10.803,-6.002) AB2(-10.002,-6.002) AB3(-9.202,-6.002) AB4(-8.402,-6.002) AB5(-7.602,-6.002) AB6(-6.802,-6.002) AB7(-6.002,-6.002) AB8(-5.202,-6.002) AB9(-4.402,-6.002) AB10(-3.602,-6.002) AB11(-2.802,-6.002) AB12(-2.002,-6.002) AB13(-1.201,-6.002) AB14(-0.401,-6.002) AB15(0.401,-6.002) AB16(1.201,-6.002) AB17(2.002,-6.002) AB18(2.802,-6.002) AB19(3.602,-6.002) AB20(4.402,-6.002) AB21(5.202,-6.002) AB22(6.002,-6.002) AB23(6.802,-6.002) AB24(7.602,-6.002) AB25(8.402,-6.002) AB27(10.002,-6.002) AB28(10.803,-6.002) AC1(-10.803,-6.802) AC2(-10.002,-6.802) AC3(-9.202,-6.802) AC4(-8.402,-6.802) AC5(-7.602,-6.802) AC6(-6.802,-6.802) AC7(-6.002,-6.802) AC8(-5.202,-6.802) AC9(-4.402,-6.802) AC10(-3.602,-6.802) AC11(-2.802,-6.802) AC12(-2.002,-6.802) AC13(-1.201,-6.802) AC14(-0.401,-6.802) AC15(0.401,-6.802) AC16(1.201,-6.802) AC17(2.002,-6.802) AC18(2.802,-6.802) AC19(3.602,-6.802) AC20(4.402,-6.802) AC21(5.202,-6.802) AC22(6.002,-6.802) AC23(6.802,-6.802) AC24(7.602,-6.802) AC25(8.402,-6.802) AC26(9.202,-6.802) AC27(10.002,-6.802) AC28(10.803,-6.802) AD1(-10.803,-7.602) AD2(-10.002,-7.602) AD3(-9.202,-7.602) AD4(-8.402,-7.602) AD5(-7.602,-7.602) AD6(-6.802,-7.602) AD7(-6.002,-7.602) AD8(-5.202,-7.602) AD9(-4.402,-7.602) AD10(-3.602,-7.602) AD11(-2.802,-7.602) AD12(-2.002,-7.602) AD13(-1.201,-7.602) AD14(-0.401,-7.602) AD15(0.401,-7.602) AD16(1.201,-7.602) AD17(2.002,-7.602) AD18(2.802,-7.602) AD19(3.602,-7.602) AD20(4.402,-7.602) AD21(5.202,-7.602) AD22(6.002,-7.602) AD23(6.802,-7.602) AD24(7.602,-7.602) AD25(8.402,-7.602) AD26(9.202,-7.602) AD27(10.002,-7.602) AD28(10.803,-7.602) AE1(-10.803,-8.402) AE2(-10.002,-8.402) AE3(-9.202,-8.402) AE5(-7.602,-8.402) AE6(-6.802,-8.402) AE7(-6.002,-8.402) AE8(-5.202,-8.402) AE9(-4.402,-8.402) AE10(-3.602,-8.402) AE11(-2.802,-8.402) AE12(-2.002,-8.402) AE13(-1.201,-8.402) AE14(-0.401,-8.402) AE15(0.401,-8.402) AE16(1.201,-8.402) AE17(2.002,-8.402) AE18(2.802,-8.402) AE19(3.602,-8.402) AE20(4.402,-8.402) AE21(5.202,-8.402) AE22(6.002,-8.402) AE23(6.802,-8.402) AE24(7.602,-8.402) AE26(9.202,-8.402) AE27(10.002,-8.402) AE28(10.803,-8.402) AF1(-10.803,-9.202) AF2(-10.002,-9.202) AF3(-9.202,-9.202) AF4(-8.402,-9.202) AF5(-7.602,-9.202) AF6(-6.802,-9.202) AF8(-5.202,-9.202) AF9(-4.402,-9.202) AF11(-2.802,-9.202) AF12(-2.002,-9.202) AF14(-0.401,-9.202) AF15(0.401,-9.202) AF17(2.002,-9.202) AF18(2.802,-9.202) AF20(4.402,-9.202) AF21(5.202,-9.202) AF22(6.002,-9.202) AF23(6.802,-9.202) AF24(7.602,-9.202) AF25(8.402,-9.202) AF26(9.202,-9.202) AF27(10.002,-9.202) AF28(10.803,-9.202) AG1(-10.803,-10.002) AG2(-10.002,-10.002) AG3(-9.202,-10.002) AG4(-8.402,-10.002) AG5(-7.602,-10.002) AG6(-6.802,-10.002) AG7(-6.002,-10.002) AG8(-5.202,-10.002) AG9(-4.402,-10.002) AG10(-3.602,-10.002) AG11(-2.802,-10.002) AG12(-2.002,-10.002) AG13(-1.201,-10.002) AG14(-0.401,-10.002) AG15(0.401,-10.002) AG16(1.201,-10.002) AG17(2.002,-10.002) AG18(2.802,-10.002) AG19(3.602,-10.002) AG20(4.402,-10.002) AG21(5.202,-10.002) AG22(6.002,-10.002) AG23(6.802,-10.002) AG24(7.602,-10.002) AG25(8.402,-10.002) AG26(9.202,-10.002) AG27(10.002,-10.002) AG28(10.803,-10.002) AH1(-10.803,-10.803) AH2(-10.002,-10.803) AH3(-9.202,-10.803) AH4(-8.402,-10.803) AH5(-7.602,-10.803) AH6(-6.802,-10.803) AH7(-6.002,-10.803) AH8(-5.202,-10.803) AH9(-4.402,-10.803) AH10(-3.602,-10.803) AH11(-2.802,-10.803) AH12(-2.002,-10.803) AH13(-1.201,-10.803) AH14(-0.401,-10.803) AH15(0.401,-10.803) AH16(1.201,-10.803) AH17(2.002,-10.803) AH18(2.802,-10.803) AH19(3.602,-10.803) AH20(4.402,-10.803) AH21(5.202,-10.803) AH22(6.002,-10.803) AH23(6.802,-10.803) AH24(7.602,-10.803) AH25(8.402,-10.803) AH26(9.202,-10.803) AH27(10.002,-10.803) AH28(10.803,-10.803) B1(-10.803,10.002) B2(-10.002,10.002) B3(-9.202,10.002) B4(-8.402,10.002) B5(-7.602,10.002) B6(-6.802,10.002) B7(-6.002,10.002) B8(-5.202,10.002) B9(-4.402,10.002) B10(-3.602,10.002) B11(-2.802,10.002) B12(-2.002,10.002) B13(-1.201,10.002) B14(-0.401,10.002) B15(0.401,10.002) B16(1.201,10.002) B17(2.002,10.002) B18(2.802,10.002) B19(3.602,10.002) B20(4.402,10.002) B21(5.202,10.002) B22(6.002,10.002) B23(6.802,10.002) B24(7.602,10.002) B25(8.402,10.002) B26(9.202,10.002) B27(10.002,10.002) B28(10.803,10.002) C1(-10.803,9.202) C2(-10.002,9.202) C3(-9.202,9.202) C4(-8.402,9.202) C5(-7.602,9.202) C6(-6.802,9.202) C7(-6.002,9.202) C8(-5.202,9.202) C9(-4.402,9.202) C11(-2.802,9.202) C12(-2.002,9.202) C14(-0.401,9.202) C15(0.401,9.202) C17(2.002,9.202) C18(2.802,9.202) C20(4.402,9.202) C21(5.202,9.202) C23(6.802,9.202) C24(7.602,9.202) C25(8.402,9.202) C26(9.202,9.202) C27(10.002,9.202) C28(10.803,9.202) D1(-10.803,8.402) D2(-10.002,8.402) D3(-9.202,8.402) D5(-7.602,8.402) D6(-6.802,8.402) D7(-6.002,8.402) D8(-5.202,8.402) D9(-4.402,8.402) D10(-3.602,8.402) D11(-2.802,8.402) D12(-2.002,8.402) D13(-1.201,8.402) D14(-0.401,8.402) D15(0.401,8.402) D16(1.201,8.402) D17(2.002,8.402) D18(2.802,8.402) D19(3.602,8.402) D20(4.402,8.402) D21(5.202,8.402) D22(6.002,8.402) D23(6.802,8.402) D24(7.602,8.402) D26(9.202,8.402) D27(10.002,8.402) D28(10.803,8.402) E1(-10.803,7.602) E2(-10.002,7.602) E3(-9.202,7.602) E4(-8.402,7.602) E5(-7.602,7.602) E6(-6.802,7.602) E7(-6.002,7.602) E8(-5.202,7.602) E9(-4.402,7.602) E10(-3.602,7.602) E11(-2.802,7.602) E12(-2.002,7.602) E13(-1.201,7.602) E14(-0.401,7.602) E15(0.401,7.602) E16(1.201,7.602) E17(2.002,7.602) E18(2.802,7.602) E19(3.602,7.602) E20(4.402,7.602) E21(5.202,7.602) E22(6.002,7.602) E23(6.802,7.602) E24(7.602,7.602) E25(8.402,7.602) E26(9.202,7.602) E27(10.002,7.602) E28(10.803,7.602) F1(-10.803,6.802) F2(-10.002,6.802) F3(-9.202,6.802) F4(-8.402,6.802) F5(-7.602,6.802) F6(-6.802,6.802) F7(-6.002,6.802) F8(-5.202,6.802) F9(-4.402,6.802) F10(-3.602,6.802) F11(-2.802,6.802) F12(-2.002,6.802) F13(-1.201,6.802) F14(-0.401,6.802) F15(0.401,6.802) F16(1.201,6.802) F17(2.002,6.802) F18(2.802,6.802) F19(3.602,6.802) F20(4.402,6.802) F21(5.202,6.802) F22(6.002,6.802) F23(6.802,6.802) F24(7.602,6.802) F25(8.402,6.802) F26(9.202,6.802) F27(10.002,6.802) F28(10.803,6.802) G1(-10.803,6.002) G2(-10.002,6.002) G4(-8.402,6.002) G5(-7.602,6.002) G6(-6.802,6.002) G7(-6.002,6.002) G8(-5.202,6.002) G9(-4.402,6.002) G10(-3.602,6.002) G11(-2.802,6.002) G12(-2.002,6.002) G13(-1.201,6.002) G14(-0.401,6.002) G15(0.401,6.002) G16(1.201,6.002) G17(2.002,6.002) G18(2.802,6.002) G19(3.602,6.002) G20(4.402,6.002) G21(5.202,6.002) G22(6.002,6.002) G23(6.802,6.002) G24(7.602,6.002) G25(8.402,6.002) G26(9.202,6.002) G27(10.002,6.002) G28(10.803,6.002) H1(-10.803,5.202) H2(-10.002,5.202) H3(-9.202,5.202) H4(-8.402,5.202) H5(-7.602,5.202) H6(-6.802,5.202) H7(-6.002,5.202) H8(-5.202,5.202) H9(-4.402,5.202) H10(-3.602,5.202) H11(-2.802,5.202) H12(-2.002,5.202) H13(-1.201,5.202) H14(-0.401,5.202) H15(0.401,5.202) H16(1.201,5.202) H17(2.002,5.202) H18(2.802,5.202) H19(3.602,5.202) H20(4.402,5.202) H21(5.202,5.202) H22(6.002,5.202) H23(6.802,5.202) H24(7.602,5.202) H25(8.402,5.202) H26(9.202,5.202) H27(10.002,5.202) H28(10.803,5.202) J1(-10.803,4.402) J2(-10.002,4.402) J3(-9.202,4.402) J4(-8.402,4.402) J5(-7.602,4.402) J6(-6.802,4.402) J7(-6.002,4.402) J8(-5.202,4.402) J9(-4.402,4.402) J10(-3.602,4.402) J11(-2.802,4.402) J12(-2.002,4.402) J13(-1.201,4.402) J14(-0.401,4.402) J15(0.401,4.402) J16(1.201,4.402) J17(2.002,4.402) J18(2.802,4.402) J19(3.602,4.402) J20(4.402,4.402) J21(5.202,4.402) J22(6.002,4.402) J23(6.802,4.402) J24(7.602,4.402) J25(8.402,4.402) J26(9.202,4.402) J27(10.002,4.402) J28(10.803,4.402) K1(-10.803,3.602) K2(-10.002,3.602) K4(-8.402,3.602) K5(-7.602,3.602) K6(-6.802,3.602) K7(-6.002,3.602) K8(-5.202,3.602) K9(-4.402,3.602) K10(-3.602,3.602) K11(-2.802,3.602) K12(-2.002,3.602) K13(-1.201,3.602) K14(-0.401,3.602) K15(0.401,3.602) K16(1.201,3.602) K17(2.002,3.602) K18(2.802,3.602) K19(3.602,3.602) K20(4.402,3.602) K21(5.202,3.602) K22(6.002,3.602) K23(6.802,3.602) K24(7.602,3.602) K25(8.402,3.602) K27(10.002,3.602) K28(10.803,3.602) L1(-10.803,2.802) L2(-10.002,2.802) L3(-9.202,2.802) L4(-8.402,2.802) L5(-7.602,2.802) L6(-6.802,2.802) L7(-6.002,2.802) L8(-5.202,2.802) L9(-4.402,2.802) L10(-3.602,2.802) L11(-2.802,2.802) L12(-2.002,2.802) L13(-1.201,2.802) L14(-0.401,2.802) L15(0.401,2.802) L16(1.201,2.802) L17(2.002,2.802) L18(2.802,2.802) L19(3.602,2.802) L20(4.402,2.802) L21(5.202,2.802) L22(6.002,2.802) L23(6.802,2.802) L24(7.602,2.802) L25(8.402,2.802) L26(9.202,2.802) L27(10.002,2.802) L28(10.803,2.802) M1(-10.803,2.002) M2(-10.002,2.002) M3(-9.202,2.002) M4(-8.402,2.002) M5(-7.602,2.002) M6(-6.802,2.002) M7(-6.002,2.002) M8(-5.202,2.002) M9(-4.402,2.002) M10(-3.602,2.002) M11(-2.802,2.002) M12(-2.002,2.002) M13(-1.201,2.002) M14(-0.401,2.002) M15(0.401,2.002) M16(1.201,2.002) M17(2.002,2.002) M18(2.802,2.002) M19(3.602,2.002) M20(4.402,2.002) M21(5.202,2.002) M22(6.002,2.002) M23(6.802,2.002) M24(7.602,2.002) M25(8.402,2.002) M26(9.202,2.002) M27(10.002,2.002) M28(10.803,2.002) N1(-10.803,1.201) N2(-10.002,1.201) N4(-8.402,1.201) N5(-7.602,1.201) N6(-6.802,1.201) N7(-6.002,1.201) N8(-5.202,1.201) N9(-4.402,1.201) N10(-3.602,1.201) N11(-2.802,1.201) N12(-2.002,1.201) N13(-1.201,1.201) N14(-0.401,1.201) N15(0.401,1.201) N16(1.201,1.201) N17(2.002,1.201) N18(2.802,1.201) N19(3.602,1.201) N20(4.402,1.201) N21(5.202,1.201) N22(6.002,1.201) N23(6.802,1.201) N24(7.602,1.201) N25(8.402,1.201) N27(10.002,1.201) N28(10.803,1.201) P1(-10.803,0.401) P2(-10.002,0.401) P3(-9.202,0.401) P4(-8.402,0.401) P5(-7.602,0.401) P6(-6.802,0.401) P7(-6.002,0.401) P8(-5.202,0.401) P9(-4.402,0.401) P10(-3.602,0.401) P11(-2.802,0.401) P12(-2.002,0.401) P13(-1.201,0.401) P14(-0.401,0.401) P15(0.401,0.401) P16(1.201,0.401) P17(2.002,0.401) P18(2.802,0.401) P19(3.602,0.401) P20(4.402,0.401) P21(5.202,0.401) P22(6.002,0.401) P23(6.802,0.401) P24(7.602,0.401) P25(8.402,0.401) P26(9.202,0.401) P27(10.002,0.401) P28(10.803,0.401) R1(-10.803,-0.401) R2(-10.002,-0.401) R3(-9.202,-0.401) R4(-8.402,-0.401) R5(-7.602,-0.401) R6(-6.802,-0.401) R7(-6.002,-0.401) R8(-5.202,-0.401) R9(-4.402,-0.401) R10(-3.602,-0.401) R11(-2.802,-0.401) R12(-2.002,-0.401) R13(-1.201,-0.401) R14(-0.401,-0.401) R15(0.401,-0.401) R16(1.201,-0.401) R17(2.002,-0.401) R18(2.802,-0.401) R19(3.602,-0.401) R20(4.402,-0.401) R21(5.202,-0.401) R22(6.002,-0.401) R23(6.802,-0.401) R24(7.602,-0.401) R25(8.402,-0.401) R26(9.202,-0.401) R27(10.002,-0.401) R28(10.803,-0.401) T1(-10.803,-1.201) T2(-10.002,-1.201) T4(-8.402,-1.201) T5(-7.602,-1.201) T6(-6.802,-1.201) T7(-6.002,-1.201) T8(-5.202,-1.201) T9(-4.402,-1.201) T10(-3.602,-1.201) T11(-2.802,-1.201) T12(-2.002,-1.201) T13(-1.201,-1.201) T14(-0.401,-1.201) T15(0.401,-1.201) T16(1.201,-1.201) T17(2.002,-1.201) T18(2.802,-1.201) T19(3.602,-1.201) T20(4.402,-1.201) T21(5.202,-1.201) T22(6.002,-1.201) T23(6.802,-1.201) T24(7.602,-1.201) T25(8.402,-1.201) T27(10.002,-1.201) T28(10.803,-1.201) U1(-10.803,-2.002) U2(-10.002,-2.002) U3(-9.202,-2.002) U4(-8.402,-2.002) U5(-7.602,-2.002) U6(-6.802,-2.002) U7(-6.002,-2.002) U8(-5.202,-2.002) U9(-4.402,-2.002) U10(-3.602,-2.002) U11(-2.802,-2.002) U12(-2.002,-2.002) U13(-1.201,-2.002) U14(-0.401,-2.002) U15(0.401,-2.002) U16(1.201,-2.002) U17(2.002,-2.002) U18(2.802,-2.002) U19(3.602,-2.002) U20(4.402,-2.002) U21(5.202,-2.002) U22(6.002,-2.002) U23(6.802,-2.002) U24(7.602,-2.002) U25(8.402,-2.002) U26(9.202,-2.002) U27(10.002,-2.002) U28(10.803,-2.002) V1(-10.803,-2.802) V2(-10.002,-2.802) V3(-9.202,-2.802) V4(-8.402,-2.802) V5(-7.602,-2.802) V6(-6.802,-2.802) V7(-6.002,-2.802) V8(-5.202,-2.802) V9(-4.402,-2.802) V10(-3.602,-2.802) V11(-2.802,-2.802) V12(-2.002,-2.802) V13(-1.201,-2.802) V14(-0.401,-2.802) V15(0.401,-2.802) V16(1.201,-2.802) V17(2.002,-2.802) V18(2.802,-2.802) V19(3.602,-2.802) V20(4.402,-2.802) V21(5.202,-2.802) V22(6.002,-2.802) V23(6.802,-2.802) V24(7.602,-2.802) V25(8.402,-2.802) V26(9.202,-2.802) V27(10.002,-2.802) V28(10.803,-2.802) W1(-10.803,-3.602) W2(-10.002,-3.602) W4(-8.402,-3.602) W5(-7.602,-3.602) W6(-6.802,-3.602) W7(-6.002,-3.602) W8(-5.202,-3.602) W9(-4.402,-3.602) W10(-3.602,-3.602) W11(-2.802,-3.602) W12(-2.002,-3.602) W13(-1.201,-3.602) W14(-0.401,-3.602) W15(0.401,-3.602) W16(1.201,-3.602) W17(2.002,-3.602) W18(2.802,-3.602) W19(3.602,-3.602) W20(4.402,-3.602) W21(5.202,-3.602) W22(6.002,-3.602) W23(6.802,-3.602) W24(7.602,-3.602) W25(8.402,-3.602) W27(10.002,-3.602) W28(10.803,-3.602) Y1(-10.803,-4.402) Y2(-10.002,-4.402) Y3(-9.202,-4.402) Y4(-8.402,-4.402) Y5(-7.602,-4.402) Y6(-6.802,-4.402) Y7(-6.002,-4.402) Y8(-5.202,-4.402) Y9(-4.402,-4.402) Y10(-3.602,-4.402) Y11(-2.802,-4.402) Y12(-2.002,-4.402) Y13(-1.201,-4.402) Y14(-0.401,-4.402) Y15(0.401,-4.402) Y16(1.201,-4.402) Y17(2.002,-4.402) Y18(2.802,-4.402) Y19(3.602,-4.402) Y20(4.402,-4.402) Y21(5.202,-4.402) Y22(6.002,-4.402) Y23(6.802,-4.402) Y24(7.602,-4.402) Y25(8.402,-4.402) Y26(9.202,-4.402) Y27(10.002,-4.402) Y28(10.803,-4.402)
C402-6P6SPC
  round 0.635 smd: 1(-0.508,0) 2(0.508,0)
C402-25
  round 0.635 smd: 1(-0.508,0) 2(0.508,0)
C603-6P6SPC
  oval 0.889x1.143 smd: 1(-0.762,0) 2(0.762,0)
C603-35X45
  oval 0.889x1.143 smd: 1(-0.762,0) 2(0.762,0)
C805-6P6SPC
  oval 0.889x1.524 smd: 1(-0.965,0) 2(0.965,0)
C805-35X60
  oval 0.889x1.524 smd: 1(-0.965,0) 2(0.965,0)
C1206-6P6SPC
  oval 1.016x1.778 smd: 1(-1.524,0) 2(1.524,0)
C1206-40X70
  oval 1.016x1.778 smd: 1(-1.524,0) 2(1.524,0)
C1206-40X70-POL
  oval 1.016x1.778 smd: 1(-1.524,0) 2(1.524,0)
C1210-70X102
  rect 1.778x3.048 smd: 1(-1.803,0) 2(1.803,0)
C1210-C7343-DUAL
  rect 3.429x2.997 smd: 1(-2.616,0) 2(2.616,0)
C7343-84X118
  rect 2.134x2.997 smd: 1(-3.251,0) 2(3.251,0)
CHOKE-POWER-WE-HCC
  rect 2.286x3.607 smd: 1(-4.585,0) 2(4.585,0)
CONN2X5-AMP104652
  round 1.016 hole 1.346 unplated: (-4.064,0) (4.064,0)
  rect 0.737x2.794 smd: 1(-2.54,1.651) 2(-2.54,-1.651) 3(-1.27,1.651) 4(-1.27,-1.651) 5(0,1.651) 6(0,-1.651) 7(1.27,1.651) 8(1.27,-1.651) 9(2.54,1.651) 10(2.54,-1.651)
DAP38
  oval 0.356x1.778 smd: 1(-5.852,-3.81) 2(-5.202,-3.81) 3(-4.551,-3.81) 4(-3.901,-3.81) 5(-3.251,-3.81) 6(-2.601,-3.81) 7(-1.95,-3.81) 8(-1.3,-3.81) 9(-0.65,-3.81) 10(0.001,-3.81) 11(0.65,-3.81) 12(1.301,-3.81) 13(1.951,-3.81) 14(2.601,-3.81) 15(3.252,-3.81) 16(3.902,-3.81) 17(4.55,-3.81) 18(5.2,-3.81) 19(5.85,-3.81) 20(5.851,3.81) 21(5.201,3.81) 22(4.551,3.81) 23(3.9,3.81) 24(3.25,3.81) 25(2.6,3.81) 26(1.95,3.81) 27(1.3,3.81) 28(0.649,3.81) 29(-0.001,3.81) 30(-0.651,3.81) 31(-1.302,3.81) 32(-1.952,3.81) 33(-2.6,3.81) 34(-3.25,3.81) 35(-3.9,3.81) 36(-4.55,3.81) 37(-5.2,3.81) 38(-5.85,3.81)
  rect 10.998x5.004 smd: 39(0,0)
DBV5-27X39
  rect 0.686x0.991 smd: 1(-0.95,-1.321) 2(0,-1.321) 3(0.95,-1.321) 4(0.95,1.321) 5(-0.95,1.321)
DBV6-27X39-6
  rect 0.686x0.991 smd: 1(-0.95,-1.321) 2(0,-1.321) 3(0.95,-1.321) 4(0.95,1.321) 5(0,1.321) 6(-0.95,1.321)
DCK-5
  rect 0.46x0.66 smd: 1(-0.65,-0.991) 2(0,-0.991) 3(0.65,-0.991) 4(0.65,0.991) 5(-0.65,0.991)
DCK-17X60-6
  rect 0.46x0.66 smd: 1(-0.65,-0.991) 2(0,-0.991) 3(0.65,-0.991) 4(0.65,0.991) 5(0,0.991) 6(-0.65,0.991)
DCT8-14X70
  oval 0.356x1.778 smd: 1(-0.975,-1.844) 2(-0.325,-1.844) 3(0.325,-1.844) 4(0.975,-1.844) 5(0.975,1.841) 6(0.325,1.841) 7(-0.325,1.841) 8(-0.975,1.841)
DCU8-10X50
  oval 0.254x1.27 smd: 1(-0.747,-1.499) 2(-0.249,-1.499) 3(0.249,-1.499) 4(0.747,-1.499) 5(0.747,1.499) 6(0.249,1.499) 7(-0.249,1.499) 8(-0.747,1.499)
DPAK3-55X120-4
  rect 1.397x3.048 smd: 1(-2.54,-6.413) 3(2.54,-6.413)
  rect 10.541x7.696 smd: 4(0,3.607)
DRC10-11X33
  rect 0.305x0.762 smd: 1(-1.001,-1.473) 2(-0.5,-1.473) 3(0,-1.473) 4(0.5,-1.473) 5(1.001,-1.473) 6(1.001,1.473) 7(0.5,1.473) 8(0,1.473) 9(-0.5,1.473) 10(-1.001,1.473)
  custom 0.406x0.406 smd: 11(0,0)
DRL5-12X40
  rect 0.305x1.016 smd: 1(-0.5,-0.813) 2(0,-0.813) 3(0.5,-0.813) 4(0.5,0.813) 5(-0.5,0.813)
DRL6-12X30
  rect 0.305x0.762 smd: 1(-0.5,-0.813) 2(0,-0.813) 3(0.5,-0.813) 4(0.5,0.813) 5(0,0.813) 6(-0.5,0.813)
DSG8-11X20
  rect 0.279x0.508 smd: 1(-0.75,-0.965) 2(-0.25,-0.965) 3(0.25,-0.965) 4(0.75,-0.965) 5(0.75,0.965) 6(0.25,0.965) 7(-0.25,0.965) 8(-0.75,0.965)
  rect 1.6x0.889 smd: 9(0,0)
DSQ10-SON
  rect 0.229x0.711 smd: 1(-0.8,-1.067) 2(-0.399,-1.067) 3(0,-1.067) 4(0.399,-1.067) 5(0.8,-1.067) 6(0.8,1.067) 7(0.399,1.067) 8(0,1.067) 9(-0.399,1.067) 10(-0.8,1.067)
  rect 1.524x0.889 smd: 11(0,0)
EMI-36X15-DLW21
  rect 0.914x0.381 smd: 1(-0.838,0.406) 2(0.838,0.406) 3(0.838,-0.406) 4(-0.838,-0.406)
EMI-NFM21P
  rect 0.889x0.813 smd: 1(-1.118,0) 3(1.118,0)
  rect 0.508x2.007 smd: 2(0,0)
FBGA153-169-P5-COMBO
  round 0.254 smd: A1(-3.249,3.249) A2(-2.749,3.249) A3(-2.249,3.249) A4(-1.75,3.249) A5(-1.25,3.249) A6(-0.75,3.249) A7(-0.25,3.249) A8(0.25,3.249) A9(0.75,3.249) A10(1.25,3.249) A11(1.75,3.249) A12(2.249,3.249) A13(2.749,3.249) A14(3.249,3.249) B1(-3.249,2.749) B2(-2.749,2.749) B3(-2.249,2.749) B4(-1.75,2.749) B5(-1.25,2.749) B6(-0.75,2.749) B7(-0.25,2.749) B8(0.25,2.749) B9(0.75,2.749) B10(1.25,2.749) B11(1.75,2.749) B12(2.249,2.749) B13(2.749,2.749) B14(3.249,2.749) C1(-3.249,2.249) C2(-2.749,2.249) C3(-2.249,2.249) C4(-1.75,2.249) C5(-1.25,2.249) C6(-0.75,2.249) C7(-0.25,2.249) C8(0.25,2.249) C9(0.75,2.249) C10(1.25,2.249) C11(1.75,2.249) C12(2.249,2.249) C13(2.749,2.249) C14(3.249,2.249) D1(-3.249,1.75) D2(-2.749,1.75) D3(-2.249,1.75) D4(-1.75,1.75) D12(2.249,1.75) D13(2.749,1.75) D14(3.249,1.75) E1(-3.249,1.25) E2(-2.749,1.25) E3(-2.249,1.25) E5(-1.25,1.25) E6(-0.75,1.25) E7(-0.25,1.25) E8(0.25,1.25) E9(0.75,1.25) E10(1.25,1.25) E12(2.249,1.25) E13(2.749,1.25) E14(3.249,1.25) F1(-3.249,0.75) F2(-2.749,0.75) F3(-2.249,0.75) F5(-1.25,0.75) F10(1.25,0.75) F12(2.249,0.75) F13(2.749,0.75) F14(3.249,0.75) G1(-3.249,0.25) G2(-2.749,0.25) G3(-2.249,0.25) G5(-1.25,0.25) G10(1.25,0.25) G12(2.249,0.25) G13(2.749,0.25) G14(3.249,0.25) H1(-3.249,-0.25) H2(-2.749,-0.25) H3(-2.249,-0.25) H5(-1.25,-0.25) H10(1.25,-0.25) H12(2.249,-0.25) H13(2.749,-0.25) H14(3.249,-0.25) J1(-3.249,-0.75) J2(-2.749,-0.75) J3(-2.249,-0.75) J5(-1.25,-0.75) J10(1.25,-0.75) J12(2.249,-0.75) J13(2.749,-0.75) J14(3.249,-0.75) K1(-3.249,-1.25) K2(-2.749,-1.25) K3(-2.249,-1.25) K5(-1.25,-1.25) K6(-0.75,-1.25) K7(-0.25,-1.25) K8(0.25,-1.25) K9(0.75,-1.25) K10(1.25,-1.25) K12(2.249,-1.25) K13(2.749,-1.25) K14(3.249,-1.25) L1(-3.249,-1.75) L2(-2.749,-1.75) L3(-2.249,-1.75) L12(2.249,-1.75) L13(2.749,-1.75) L14(3.249,-1.75) M1(-3.249,-2.249) M2(-2.749,-2.249) M3(-2.249,-2.249) M4(-1.75,-2.249) M5(-1.25,-2.249) M6(-0.75,-2.249) M7(-0.25,-2.249) M8(0.25,-2.249) M9(0.75,-2.249) M10(1.25,-2.249) M11(1.75,-2.249) M12(2.249,-2.249) M13(2.749,-2.249) M14(3.249,-2.249) MA4(-1.75,6.748) MA6(-0.75,6.748) MA9(0.75,6.748) MA11(1.75,6.748) MAE1(-3.249,-5.249) MAE14(3.249,-5.249) MAG2(-2.749,-6.248) MAG13(2.749,-6.248) MAH4(-1.75,-6.748) MAH6(-0.75,-6.748) MAH9(0.75,-6.748) MAH11(1.75,-6.748) MB2(-2.749,6.248) MB13(2.749,6.248) MD1(-3.249,5.249) MD14(3.249,5.249) N1(-3.249,-2.749) N2(-2.749,-2.749) N3(-2.249,-2.749) N4(-1.75,-2.749) N5(-1.25,-2.749) N6(-0.75,-2.749) N7(-0.25,-2.749) N8(0.25,-2.749) N9(0.75,-2.749) N10(1.25,-2.749) N11(1.75,-2.749) N12(2.249,-2.749) N13(2.749,-2.749) N14(3.249,-2.749) P1(-3.249,-3.249) P2(-2.749,-3.249) P3(-2.249,-3.249) P4(-1.75,-3.249) P5(-1.25,-3.249) P6(-0.75,-3.249) P7(-0.25,-3.249) P8(0.25,-3.249) P9(0.75,-3.249) P10(1.25,-3.249) P11(1.75,-3.249) P12(2.249,-3.249) P13(2.749,-3.249) P14(3.249,-3.249)
FUSEFOLDER-OMNI-BLOK
  rect 4.242x3.81 smd: 1(-3.2,0) 2(3.2,0)
IND2-65X90-IHLP1616
  rect 1.651x2.286 smd: 1(-1.651,0) 2(1.651,0)
IND2-115X213-12MM
  rect 2.921x5.41 smd: 1(-4.978,0) 2(4.978,0)
JUMP1X2-5635-2MM
  rect 1.422x1.422 hole 0.889: 1(0,0)
  round 1.422 hole 0.889: 2(1.981,0)
L603-35X45
  oval 0.889x1.143 smd: 1(-0.762,0) 2(0.762,0)
L805-35X60
  oval 0.889x1.524 smd: 1(-0.965,0) 2(0.965,0)
MEC6-150-RA1
  round 0.508 hole 1.549 unplated: (0,18.344) (0,-18.344)
  rect 2.007x0.399 smd: 1(-4,17.145) 2(4,17.145) 3(-4,16.51) 4(4,16.51) 5(-4,15.875) 6(4,15.875) 7(-4,15.24) 8(4,15.24) 9(-4,14.605) 10(4,14.605) 11(-4,13.97) 12(4,13.97) 13(-4,13.335) 14(4,13.335) 15(-4,12.7) 16(4,12.7) 17(-4,12.065) 18(4,12.065) 19(-4,11.43) 20(4,11.43) 21(-4,10.795) 22(4,10.795) 23(-4,10.16) 24(4,10.16) 25(-4,9.525) 26(4,9.525) 27(-4,8.89) 28(4,8.89) 29(-4,8.255) 30(4,8.255) 31(-4,7.62) 32(4,7.62) 33(-4,6.985) 34(4,6.985) 35(-4,6.35) 36(4,6.35) 37(-4,5.715) 38(4,5.715) 39(-4,5.08) 40(4,5.08) 41(-4,4.445) 42(4,4.445) 43(-4,3.81) 44(4,3.81) 45(-4,3.175) 46(4,3.175) 47(-4,2.54) 48(4,2.54) 49(-4,1.905) 50(4,1.905) 51(-4,1.27) 52(4,1.27) 53(-4,0.635) 54(4,0.635) 55(-4,0) 56(4,0) 57(-4,-0.635) 58(4,-0.635) 59(-4,-1.27) 60(4,-1.27) 61(-4,-1.905) 62(4,-1.905) 63(-4,-5.715) 64(4,-5.715) 65(-4,-6.35) 66(4,-6.35) 67(-4,-6.985) 68(4,-6.985) 69(-4,-7.62) 70(4,-7.62) 71(-4,-8.255) 72(4,-8.255) 73(-4,-8.89) 74(4,-8.89) 75(-4,-9.525) 76(4,-9.525) 77(-4,-10.16) 78(4,-10.16) 79(-4,-10.795) 80(4,-10.795) 81(-4,-11.43) 82(4,-11.43) 83(-4,-12.065) 84(4,-12.065) 85(-4,-12.7) 86(4,-12.7) 87(-4,-13.335) 88(4,-13.335) 89(-4,-13.97) 90(4,-13.97) 91(-4,-14.605) 92(4,-14.605) 93(-4,-15.24) 94(4,-15.24) 95(-4,-15.875) 96(4,-15.875) 97(-4,-16.51) 98(4,-16.51) 99(-4,-17.145) 100(4,-17.145)
MOLEX-49225-201
  rect 0.787x1.778 smd: 1(-3.876,10.744) 2(-2.776,10.744) 3(-1.676,10.744) 4(-0.577,10.744) 5(0.523,10.744) 6(1.623,10.744) 7(2.723,10.744) 8(3.823,10.744)
  rect 1.524x2.794 smd: 9(5.893,8.153)
  rect 1.524x2.159 smd: 10(5.893,0.47)
  rect 1.753x2.21 smd: 11(5.893,-4.128) 12(-8.712,-5.144)
  rect 1.702x3.81 smd: 13(-9.398,-0.483)
  rect 1.397x3.556 smd: 14(-9.398,9.03)
  rect 1.6x1.524 smd: 15(-5.969,10.744)
